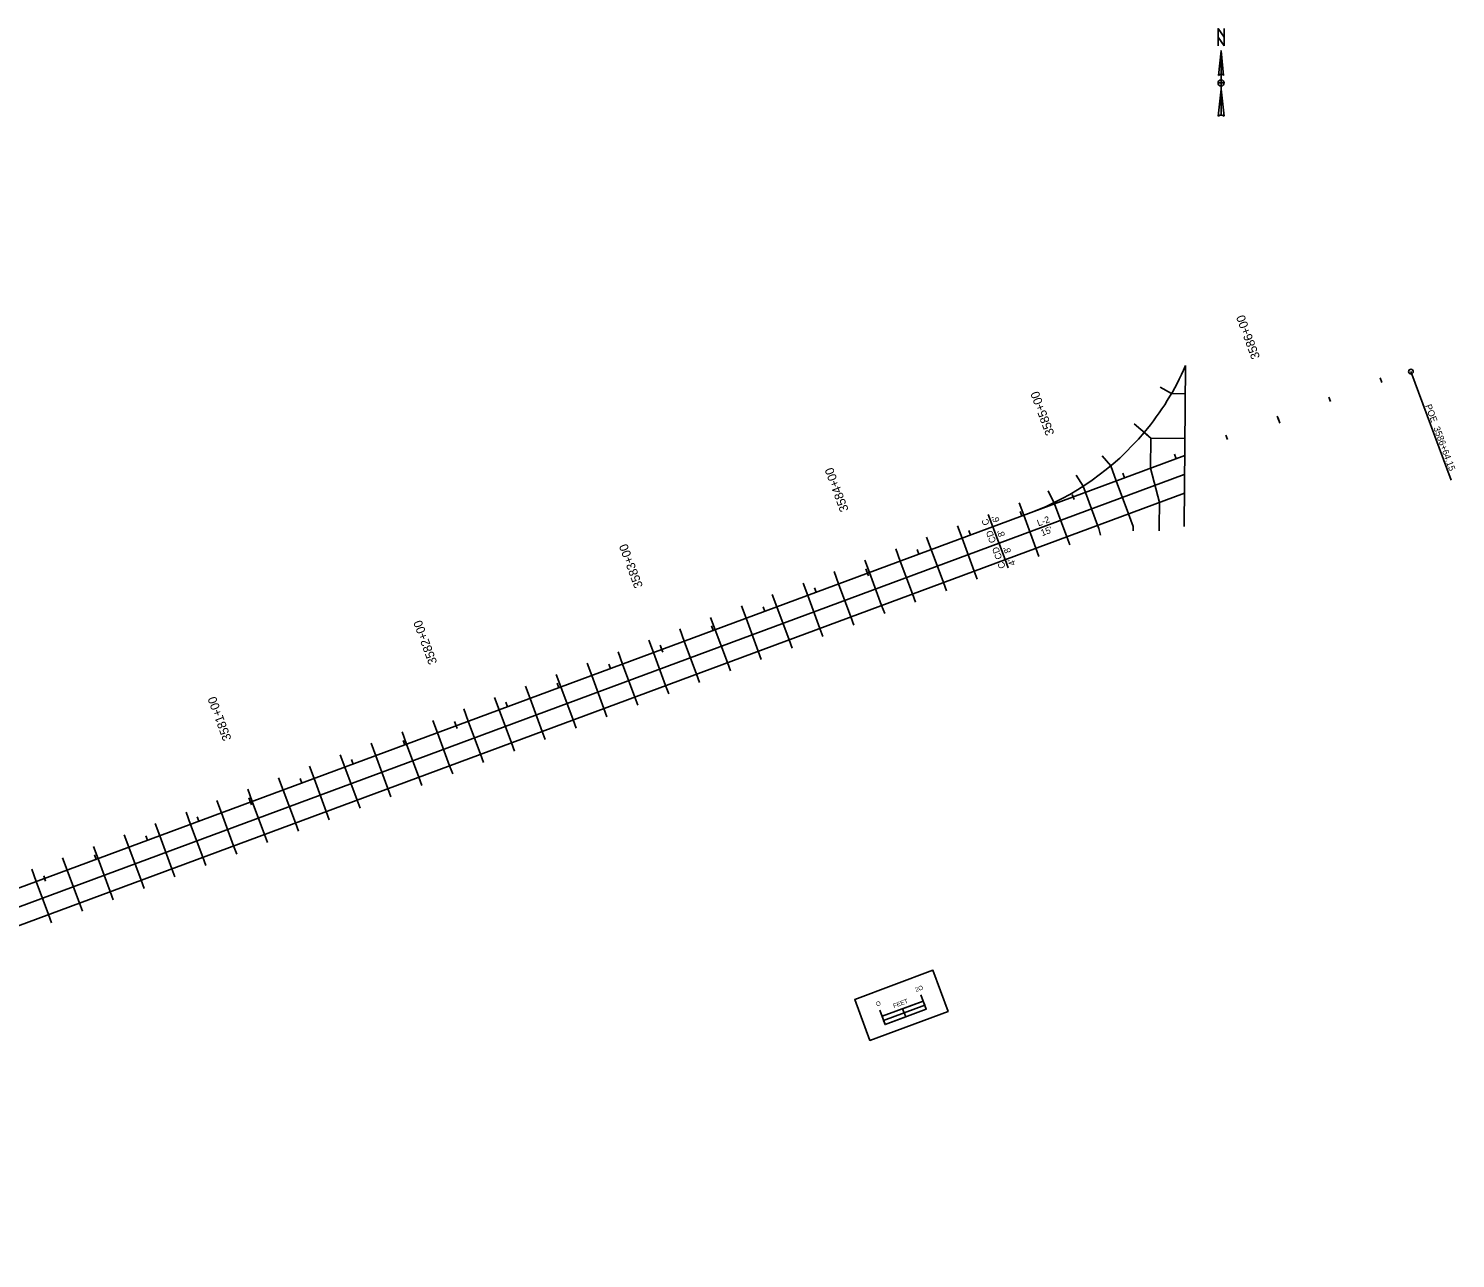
# Model space of a CAD drawing. Extents: x 19570301 to 19572259, y 7727180 to 7727858.
# Drawn here: x 19571608 to 19572259, y 7727298 to 7727858 of the extents above; entities that cross this region are included whole.
import ezdxf

# ---------------------------------------------------------------- set-up
doc = ezdxf.new("R2010")
doc.units = 0
for name, color, linetype in [('Alignment', 7, 'Continuous'), ('NamedBoundary', 7, 'Continuous'), ('Profile', 7, 'Continuous'), ('SheetText', 7, 'Continuous'), ('Terrain', 7, 'Continuous')]:
    doc.layers.add(name, color=color, linetype=linetype)

msp = doc.modelspace()

# ---------------------------------------------------------------- linework, layer by layer
at = {"layer": 'Alignment'}
for p in [(19572238.28, 7727701.72), (19572256.64, 7727652.21)]:
    msp.add_line(p, (19572256.64, 7727652.21), dxfattribs=at)
msp.add_circle((19572238.28, 7727701.72), 1.07, dxfattribs=at)
at = {"layer": 'NamedBoundary'}
for p, q in [((19572135.59, 7727704.44), (19572134.97, 7727631.18)), ((19572129.13, 7727691.68), (19572123.94, 7727694.69)), ((19572135.46, 7727691.62), (19572129.13, 7727691.68)), ((19572118.16, 7727672.81), (19572112.12, 7727677.88)), ((19572119.77, 7727671.45), (19572116.71, 7727674.02)), ((19572119.66, 7727657.73), (19572119.77, 7727671.45)), ((19572135.31, 7727671.32), (19572119.77, 7727671.45)), ((19571189.23, 7727312.65), (19572135.22, 7727663.5)), ((19572101.45, 7727658.76), (19572097.59, 7727663.36)), ((19572103.99, 7727651.91), (19572101.45, 7727658.76)), ((19572123.62, 7727642.13), (19572119.66, 7727657.73)), ((19571192.01, 7727305.15), (19572134.9, 7727654.85)), ((19572088.89, 7727649.49), (19572085.63, 7727654.53)), ((19572089.92, 7727646.7), (19572088.89, 7727649.49)), ((19572109.55, 7727636.91), (19572103.99, 7727651.91)), ((19572135.09, 7727646.38), (19571194.79, 7727297.65)), ((19572075.86, 7727641.48), (19572072.99, 7727647.41)), ((19572095.49, 7727631.7), (19572089.92, 7727646.7)), ((19572047.73, 7727631.05), (19572045.65, 7727636.68)), ((19572061.8, 7727636.27), (19572059.71, 7727641.89)), ((19572067.36, 7727621.27), (19572061.8, 7727636.27)), ((19572081.42, 7727626.48), (19572075.86, 7727641.48)), ((19572109.55, 7727636.91), (19572111.68, 7727631.19)), ((19572123.62, 7727642.13), (19572123.61, 7727631.18)), ((19572033.67, 7727625.83), (19572031.58, 7727631.46)), ((19572053.3, 7727616.05), (19572047.73, 7727631.05)), ((19572095.49, 7727631.7), (19572096.04, 7727630.22)), ((19572096.04, 7727630.22), (19572096.73, 7727627.23)), ((19572111.68, 7727631.19), (19572111.73, 7727629.16)), ((19572123.61, 7727631.18), (19572123.61, 7727629.18)), ((19572019.61, 7727620.62), (19572017.52, 7727626.24)), ((19572039.23, 7727610.83), (19572033.67, 7727625.83)), ((19572081.42, 7727626.48), (19572082.82, 7727622.73)), ((19572005.54, 7727615.4), (19572003.45, 7727621.03)), ((19572025.17, 7727605.62), (19572019.61, 7727620.62)), ((19572067.36, 7727621.27), (19572068.75, 7727617.51)), ((19571977.41, 7727604.97), (19571975.33, 7727610.6)), ((19571991.48, 7727610.19), (19571989.39, 7727615.81)), ((19571997.04, 7727595.19), (19571991.48, 7727610.19)), ((19572011.1, 7727600.4), (19572005.54, 7727615.4)), ((19572039.23, 7727610.83), (19572040.62, 7727607.08)), ((19572053.3, 7727616.05), (19572054.69, 7727612.3)), ((19571963.35, 7727599.76), (19571961.26, 7727605.38)), ((19571982.98, 7727589.97), (19571977.41, 7727604.97)), ((19572025.17, 7727605.62), (19572026.56, 7727601.87)), ((19571949.29, 7727594.54), (19571947.2, 7727600.16)), ((19571968.91, 7727584.75), (19571963.35, 7727599.76)), ((19572011.1, 7727600.4), (19572012.5, 7727596.65)), ((19571935.22, 7727589.32), (19571933.14, 7727594.95)), ((19571954.85, 7727579.54), (19571949.29, 7727594.54)), ((19571997.04, 7727595.19), (19571998.43, 7727591.44)), ((19571907.09, 7727578.89), (19571905.01, 7727584.52)), ((19571921.16, 7727584.11), (19571919.07, 7727589.73)), ((19571926.72, 7727569.11), (19571921.16, 7727584.11)), ((19571940.79, 7727574.32), (19571935.22, 7727589.32)), ((19571968.91, 7727584.75), (19571970.3, 7727581)), ((19571982.98, 7727589.97), (19571984.37, 7727586.22)), ((19571893.03, 7727573.68), (19571890.94, 7727579.3)), ((19571912.66, 7727563.89), (19571907.09, 7727578.89)), ((19571954.85, 7727579.54), (19571956.24, 7727575.79)), ((19571878.97, 7727568.46), (19571876.88, 7727574.09)), ((19571898.59, 7727558.67), (19571893.03, 7727573.68)), ((19571940.79, 7727574.32), (19571942.18, 7727570.57)), ((19571864.9, 7727563.24), (19571862.82, 7727568.87)), ((19571884.53, 7727553.46), (19571878.97, 7727568.46)), ((19571926.72, 7727569.11), (19571928.11, 7727565.36)), ((19571836.77, 7727552.81), (19571834.69, 7727558.44)), ((19571850.84, 7727558.03), (19571848.75, 7727563.65)), ((19571856.4, 7727543.03), (19571850.84, 7727558.03)), ((19571870.47, 7727548.24), (19571864.9, 7727563.24)), ((19571898.59, 7727558.67), (19571899.98, 7727554.92)), ((19571912.66, 7727563.89), (19571914.05, 7727560.14)), ((19571822.71, 7727547.6), (19571820.62, 7727553.22)), ((19571842.34, 7727537.81), (19571836.77, 7727552.81)), ((19571884.53, 7727553.46), (19571885.92, 7727549.71)), ((19571808.65, 7727542.38), (19571806.56, 7727548.01)), ((19571828.27, 7727532.59), (19571822.71, 7727547.6)), ((19571870.47, 7727548.24), (19571871.86, 7727544.49)), ((19571794.58, 7727537.16), (19571792.5, 7727542.79)), ((19571814.21, 7727527.38), (19571808.65, 7727542.38)), ((19571856.4, 7727543.03), (19571857.79, 7727539.28)), ((19571766.45, 7727526.73), (19571764.37, 7727532.36)), ((19571780.52, 7727531.95), (19571778.43, 7727537.57)), ((19571786.08, 7727516.95), (19571780.52, 7727531.95)), ((19571800.15, 7727522.16), (19571794.58, 7727537.16)), ((19571828.27, 7727532.59), (19571829.66, 7727528.84)), ((19571842.34, 7727537.81), (19571843.73, 7727534.06)), ((19571752.39, 7727521.52), (19571750.3, 7727527.14)), ((19571772.02, 7727511.73), (19571766.45, 7727526.73)), ((19571814.21, 7727527.38), (19571815.6, 7727523.63)), ((19571738.33, 7727516.3), (19571736.24, 7727521.93)), ((19571757.95, 7727506.51), (19571752.39, 7727521.52)), ((19571800.15, 7727522.16), (19571801.54, 7727518.41)), ((19571724.26, 7727511.08), (19571722.18, 7727516.71)), ((19571743.89, 7727501.3), (19571738.33, 7727516.3)), ((19571786.08, 7727516.95), (19571787.47, 7727513.2)), ((19571696.13, 7727500.65), (19571694.05, 7727506.28)), ((19571710.2, 7727505.87), (19571708.11, 7727511.49)), ((19571715.76, 7727490.87), (19571710.2, 7727505.87)), ((19571729.83, 7727496.08), (19571724.26, 7727511.08)), ((19571757.95, 7727506.51), (19571759.35, 7727502.76)), ((19571772.02, 7727511.73), (19571773.41, 7727507.98)), ((19571682.07, 7727495.44), (19571679.98, 7727501.06)), ((19571701.7, 7727485.65), (19571696.13, 7727500.65)), ((19571743.89, 7727501.3), (19571745.28, 7727497.55)), ((19571668.01, 7727490.22), (19571665.92, 7727495.85)), ((19571687.63, 7727480.44), (19571682.07, 7727495.44)), ((19571729.83, 7727496.08), (19571731.22, 7727492.33)), ((19571653.94, 7727485), (19571651.86, 7727490.63)), ((19571673.57, 7727475.22), (19571668.01, 7727490.22)), ((19571715.76, 7727490.87), (19571717.15, 7727487.12)), ((19571625.82, 7727474.57), (19571623.73, 7727480.2)), ((19571639.88, 7727479.79), (19571637.79, 7727485.41)), ((19571645.44, 7727464.79), (19571639.88, 7727479.79)), ((19571659.51, 7727470), (19571653.94, 7727485)), ((19571687.63, 7727480.44), (19571689.03, 7727476.68)), ((19571701.7, 7727485.65), (19571703.09, 7727481.9)), ((19571611.75, 7727469.36), (19571609.66, 7727474.98)), ((19571631.38, 7727459.57), (19571625.82, 7727474.57)), ((19571673.57, 7727475.22), (19571674.96, 7727471.47)), ((19571617.31, 7727454.36), (19571611.75, 7727469.36)), ((19571659.51, 7727470), (19571660.9, 7727466.25)), ((19571645.44, 7727464.79), (19571646.83, 7727461.04)), ((19571617.31, 7727454.36), (19571618.71, 7727450.6)), ((19571631.38, 7727459.57), (19571632.77, 7727455.82)), ((19572008, 7727407.69), (19572006.6, 7727411.44)), ((19572008, 7727407.69), (19572006.6, 7727411.44))]:
    msp.add_line(p, q, dxfattribs=at)
for points in [[(19571984.76, 7727415.71), (19572020.38, 7727428.93), (19572027.34, 7727410.18), (19571991.71, 7727396.96)], [(19571991.71, 7727396.96), (19571984.76, 7727415.71), (19572020.38, 7727428.93), (19572027.34, 7727410.18)], [(19572007.29, 7727409.58), (19572016.67, 7727413.06), (19572015.98, 7727414.92), (19572006.6, 7727411.44)], [(19571998.62, 7727404.22), (19572008, 7727407.69), (19572007.29, 7727409.58), (19571997.92, 7727406.11)]]:
    msp.add_lwpolyline(points, close=True, dxfattribs=at)
for points in [[(19571996.19, 7727410.78), (19571998.62, 7727404.22), (19572017.37, 7727411.17), (19572014.94, 7727417.73)], [(19571997.23, 7727407.97), (19572015.98, 7727414.92)]]:
    msp.add_lwpolyline(points, dxfattribs=at)
for start, end in [(319.94043, 336.4042), (290.34846, 319.94043)]:
    msp.add_arc((19572021.04, 7727754.47), 125, start, end, dxfattribs=at)
at = {"layer": 'Profile'}
for p, q in [((19572151.78, 7727847.89), (19572152.9, 7727836.63)), ((19572151.78, 7727847.89), (19572151.78, 7727818.6)), ((19572150.65, 7727836.63), (19572150.65, 7727836.63)), ((19572150.69, 7727836.73), (19572150.9, 7727836.97)), ((19572151.78, 7727831.84), (19572151.78, 7727831.84)), ((19572150.37, 7727818.04), (19572151.78, 7727830.43))]:
    msp.add_line(p, q, dxfattribs=at)
msp.add_lwpolyline([(19572153.18, 7727850.15), (19572150.37, 7727854.09), (19572150.37, 7727858.03), (19572153.18, 7727854.09)], close=True, dxfattribs=at)
for points in [[(19572150.37, 7727850.15), (19572150.37, 7727858.03), (19572153.18, 7727854.09), (19572153.18, 7727858.03)], [(19572150.65, 7727836.63), (19572151.78, 7727847.89), (19572151.78, 7727837.19)], [(19572151.78, 7727831.84), (19572151.78, 7727833.25), (19572150.37, 7727833.25)], [(19572153.18, 7727833.25), (19572151.78, 7727833.25), (19572151.78, 7727834.66)], [(19572151.78, 7727818.6), (19572151.78, 7727830.43), (19572153.18, 7727818.04)]]:
    msp.add_lwpolyline(points, dxfattribs=at)
for centre, radius, start, end in [((19572151.78, 7727833.25), 1.41, 90, 180), ((19572151.78, 7727833.25), 1.41, 180, 270), ((19572151.78, 7727835.78), 1.41, 90.02039, 143.12574), ((19572151.78, 7727835.78), 1.41, 36.84806, 90.02184), ((19572151.78, 7727833.25), 1.41, 0, 90), ((19572151.78, 7727833.25), 1.41, 270, 360), ((19572151.78, 7727816.56), 2.04, 89.98939, 133.61895), ((19572151.78, 7727816.56), 2.04, 46.40206, 90.00064)]:
    msp.add_arc(centre, radius, start, end, dxfattribs=at)
at = {"layer": 'SheetText'}
for p, q in [((19572178.13, 7727679.41), (19572177.37, 7727681.46)), ((19572083.94, 7727645.79), (19572084.79, 7727643.49)), ((19571990.61, 7727609.87), (19571989.85, 7727611.91)), ((19571896.85, 7727575.09), (19571896.09, 7727577.14)), ((19571803.09, 7727540.32), (19571802.33, 7727542.37)), ((19571709.33, 7727505.55), (19571708.57, 7727507.59)), ((19571615.15, 7727471.92), (19571616, 7727469.63))]:
    msp.add_line(p, q, dxfattribs=at)
at = {"layer": 'Terrain'}
for p, q in [((19572225.01, 7727696.8), (19572224.25, 7727698.85)), ((19572201.57, 7727688.1), (19572200.81, 7727690.15)), ((19572177.7, 7727680.56), (19572178.55, 7727678.26)), ((19572154.69, 7727670.72), (19572153.93, 7727672.77)), ((19572131.25, 7727662.02), (19572130.49, 7727664.07)), ((19572107.81, 7727653.33), (19572107.05, 7727655.38)), ((19572083.94, 7727645.79), (19572084.79, 7727643.49)), ((19572060.93, 7727635.94), (19572060.17, 7727637.99)), ((19572037.49, 7727627.25), (19572036.73, 7727629.3)), ((19572014.05, 7727618.56), (19572013.29, 7727620.61)), ((19571990.18, 7727611.01), (19571991.04, 7727608.72)), ((19571967.17, 7727601.17), (19571966.41, 7727603.22)), ((19571943.73, 7727592.48), (19571942.97, 7727594.53)), ((19571920.29, 7727583.79), (19571919.53, 7727585.83)), ((19571896.42, 7727576.24), (19571897.28, 7727573.94)), ((19571873.41, 7727566.4), (19571872.65, 7727568.45)), ((19571849.97, 7727557.71), (19571849.21, 7727559.75)), ((19571826.53, 7727549.01), (19571825.77, 7727551.06)), ((19571802.66, 7727541.47), (19571803.52, 7727539.17)), ((19571779.65, 7727531.63), (19571778.89, 7727533.67)), ((19571756.21, 7727522.93), (19571755.45, 7727524.98)), ((19571732.77, 7727514.24), (19571732.01, 7727516.29)), ((19571708.91, 7727506.69), (19571709.76, 7727504.4)), ((19571685.89, 7727496.85), (19571685.13, 7727498.9)), ((19571662.45, 7727488.16), (19571661.69, 7727490.21)), ((19571639.01, 7727479.47), (19571638.25, 7727481.51)), ((19571615.15, 7727471.92), (19571616, 7727469.63))]:
    msp.add_line(p, q, dxfattribs=at)

# ---------------------------------------------------------------- texts
at = {"layer": 'Alignment'}
for s, p in [('POE ', (19572244.73, 7727686.2)), ('3586+64.15', (19572248.48, 7727676.11))]:
    msp.add_text(s, height=3, rotation=290.34846, dxfattribs=at).set_placement(p)
at = {"layer": 'NamedBoundary'}
for s, p in [('2O', (19572012.71, 7727419.04)), ('O', (19571994.88, 7727412.43)), ('FEET', (19572002.68, 7727411.7))]:
    msp.add_text(s, height=2, rotation=20.34846, dxfattribs=at).set_placement(p)
at = {"layer": 'Profile'}
for s, rotation, p in [('C', 110.34846, (19572046.31, 7727632.31)), ("6'", 110.34846, (19572050.93, 7727633.65)), ('L-2', 20.34846, (19572068.54, 7727631.19)), ("15'", 20.34846, (19572070.21, 7727626.7)), ('CD', 110.34846, (19572049.29, 7727624.27)), ("8'", 110.34846, (19572053.36, 7727627.08)), ('CD', 110.34846, (19572052.07, 7727616.77)), ("8'", 110.34846, (19572056.15, 7727619.58)), ('C', 110.34846, (19572053.61, 7727612.62)), ("4'", 110.34846, (19572058.23, 7727613.96))]:
    msp.add_text(s, height=3, rotation=rotation, dxfattribs=at).set_placement(p)
at = {"layer": 'SheetText'}
msp.add_text('3585+00', height=4.008, rotation=110.34846, dxfattribs=at).set_placement((19572075.82, 7727673.46))
at = {"layer": 'Terrain'}
for s, p in [('3586+00', (19572169.58, 7727708.24)), ('3585+00', (19572075.82, 7727673.46)), ('3584+00', (19571982.06, 7727638.69)), ('3583+00', (19571888.3, 7727603.92)), ('3582+00', (19571794.54, 7727569.14)), ('3581+00', (19571700.78, 7727534.37))]:
    msp.add_text(s, height=4.008, rotation=110.34846, dxfattribs=at).set_placement(p)

doc.saveas('drawing.dxf')
